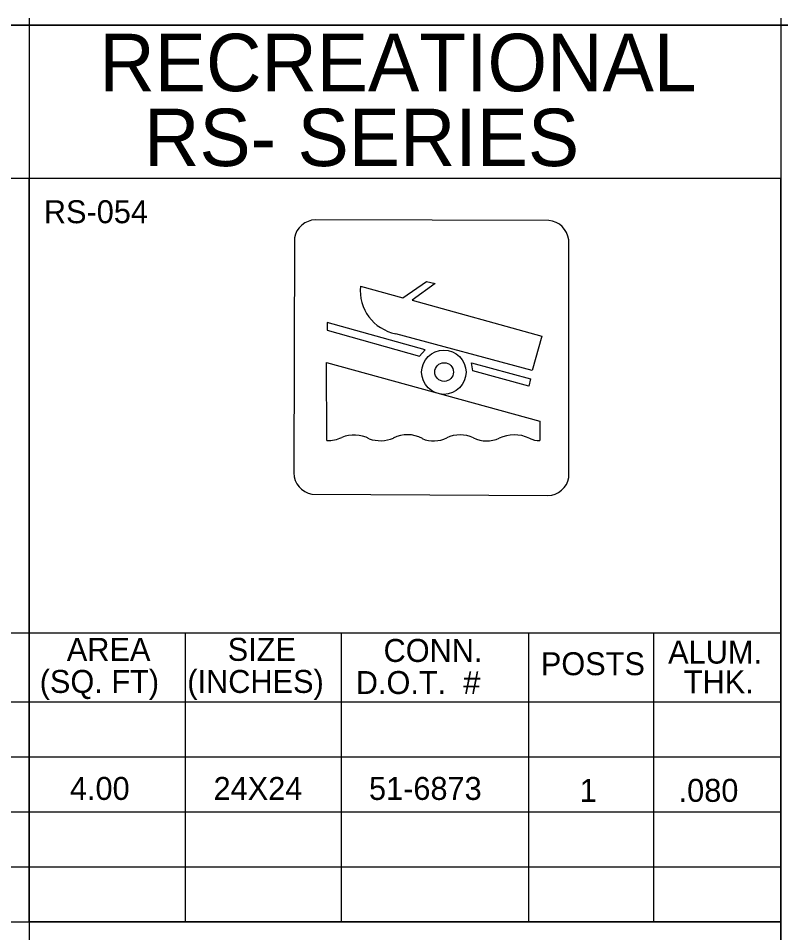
# Model space of a CAD drawing. Extents: x 0 to 2011, y -71 to 1183.
# Drawn here: x 841.5 to 947.8, y 702.6 to 830 of the extents above; entities that cross this region are included whole.
import ezdxf

# ---------------------------------------------------------------- set-up
doc = ezdxf.new("R2010")
doc.units = 0
for name, color, linetype in [('CT_Border_Perimeter_Shape', 7, 'Continuous'), ('CT_Construction', 7, 'Continuous'), ('Level 1', 7, 'Continuous'), ('Level 2', 7, 'Continuous'), ('Level 5', 7, 'Continuous')]:
    doc.layers.add(name, color=color, linetype=linetype)

msp = doc.modelspace()

# ---------------------------------------------------------------- linework, layer by layer
at = {"layer": 'CT_Border_Perimeter_Shape'}
msp.add_lwpolyline([(0, -0.97), (1270, -0.97), (1270, 829.03), (0, 829.03)], close=True, dxfattribs=at)
at = {"layer": 'CT_Construction'}
msp.add_lwpolyline([(0, 829.03), (1270, 829.03), (1270, 59.03), (0, 59.03)], close=True, dxfattribs=at)
at = {"layer": 'Level 1'}
for p, q in [((915.47, 801.83), (882.96, 801.91)), ((880.01, 799.39), (879.92, 766.64)), ((918.28, 766.01), (918.25, 799.14)), ((895.14, 791.03), (898.41, 793.34)), ((899.65, 793.03), (896.42, 790.72)), ((898.41, 793.34), (899.65, 793.03)), ((889.23, 792.65), (895.14, 791.03)), ((896.42, 790.72), (914.49, 785.69)), ((898.22, 783.78), (884.56, 787.61)), ((884.56, 787.61), (884.56, 786.52)), ((884.56, 786.52), (897.46, 782.93)), ((913.16, 780.91), (894.14, 786.04)), ((914.49, 785.69), (913.16, 780.91)), ((897.46, 782.93), (898.22, 783.78)), ((884.54, 771.16), (884.51, 782.03)), ((884.51, 782.03), (914.24, 773.86)), ((904.71, 782), (912.91, 779.77)), ((904.89, 780.89), (904.71, 782)), ((912.67, 778.75), (904.89, 780.89)), ((912.91, 779.77), (912.67, 778.75)), ((914.24, 773.86), (914.24, 771.15)), ((882.45, 763.69), (915.33, 763.49))]:
    msp.add_line(p, q, dxfattribs=at)
for centre, radius in [((900.84, 780.68), 3.09), ((900.88, 780.7), 1.3)]:
    msp.add_circle(centre, radius, dxfattribs=at)
for centre, radius, start, end in [((883.03, 798.84), 3.07, 91.4217, 169.7213), ((915.2, 798.77), 3.07, 6.7762, 85.0758), ((895.28, 792.03), 6.09, 174.1028, 259.2139), ((884.72, 775.54), 4.39, 267.5645, 295.5476), ((888.34, 767.46), 4.47, 61.8133, 112.7532), ((892.01, 775.83), 4.7, 250.6507, 292.461), ((895.76, 767.66), 4.31, 61.0182, 117.048), ((899.43, 775.25), 4.15, 247.4997, 295.889), ((903.12, 767.66), 4.29, 64.3173, 115.9152), ((906.82, 775.29), 4.19, 243.9967, 294.3106), ((910.64, 767.06), 4.89, 64.7233, 115.3716), ((914.17, 774.48), 3.33, 244.223, 271.185), ((882.99, 766.72), 3.07, 181.4217, 259.7213), ((915.26, 766.56), 3.07, 271.4217, 349.7213)]:
    msp.add_arc(centre, radius, start, end, dxfattribs=at)
at = {"layer": 'Level 2'}
for p, q in [((738.29, 744.34), (843.04, 744.34)), ((843.04, 744.34), (947.79, 744.34)), ((864.79, 744.34), (864.79, 704.06)), ((886.54, 744.34), (886.54, 704.06)), ((912.64, 744.34), (912.64, 704.06)), ((930.04, 744.34), (930.04, 704.06)), ((738.29, 734.75), (843.04, 734.75)), ((843.04, 734.75), (947.79, 734.75)), ((738.29, 727.07), (843.04, 727.07)), ((843.04, 727.07), (947.79, 727.07)), ((738.29, 719.4), (843.04, 719.4)), ((843.04, 719.4), (947.79, 719.4)), ((738.29, 711.73), (843.04, 711.73)), ((843.04, 711.73), (947.79, 711.73))]:
    msp.add_line(p, q, dxfattribs=at)
for points in [[(843.04, 807.68), (738.29, 807.68), (738.29, 704.06), (843.04, 704.06)], [(947.79, 807.68), (843.04, 807.68), (843.04, 704.06), (947.79, 704.06)], [(947.79, 704.06), (843.04, 704.06), (843.04, 600.44), (947.79, 600.44)]]:
    msp.add_lwpolyline(points, close=True, dxfattribs=at)
at = {"layer": 'Level 5'}
for p, q in [((843.04, 830), (843.04, 600.44)), ((843.04, 830), (843.04, 496.81)), ((947.79, 830), (947.79, 496.81))]:
    msp.add_line(p, q, dxfattribs=at)

# ---------------------------------------------------------------- texts
at = {"layer": 'Level 1'}
for s, p in [('RECREATIONAL', (852.83, 819.84)), ('RS- SERIES', (859.06, 809.4))]:
    msp.add_text(s, height=8, dxfattribs=at).set_placement(p)
at = {"layer": 'Level 2'}
for s, p in [('RS-054', (845.1, 801.44)), ('AREA', (848.3, 740.45)), ('SIZE', (870.72, 740.45)), ('CONN.', (892.44, 740.3)), ('ALUM.', (932.1, 740.07)), ('POSTS', (914.36, 738.45)), ('(SQ. FT)', (844.52, 735.98)), ('(INCHES)', (865.09, 735.98)), ('D.O.T.  #', (888.57, 735.83)), ('THK.', (934.28, 735.93))]:
    msp.add_text(s, height=3.2, dxfattribs=at).set_placement(p)
at = {"layer": 'Level 5'}
for s, p in [(' 4.00', (847.54, 721.07)), ('24X24', (868.75, 721.07)), ('51-6873', (890.41, 721.07)), ('1', (919.77, 720.8)), ('.080', (933.56, 720.8))]:
    msp.add_text(s, height=3.2, dxfattribs=at).set_placement(p)

doc.saveas('drawing.dxf')
